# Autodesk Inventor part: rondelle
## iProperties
Shininess: 64.0
Length Units: 11269
Angle Units: 11279
Time Units: 11290
Mass Units: 11283
Length Display Precision: 3
Angle Display Precision: 2
Compacted: True
Part Number: rondelle
Document SubType Name: Modeling
Created: 2003-05
Material: Par défaut
Designer: robert
Density: 1 g/cm^3
Density: 0.0
Volumn: 0.0
Area: 0.0
PropertySet Name: Model Information
Control State: 0
Master: False
Checked Out: False
Author: robert
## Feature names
1. Extrusion1
